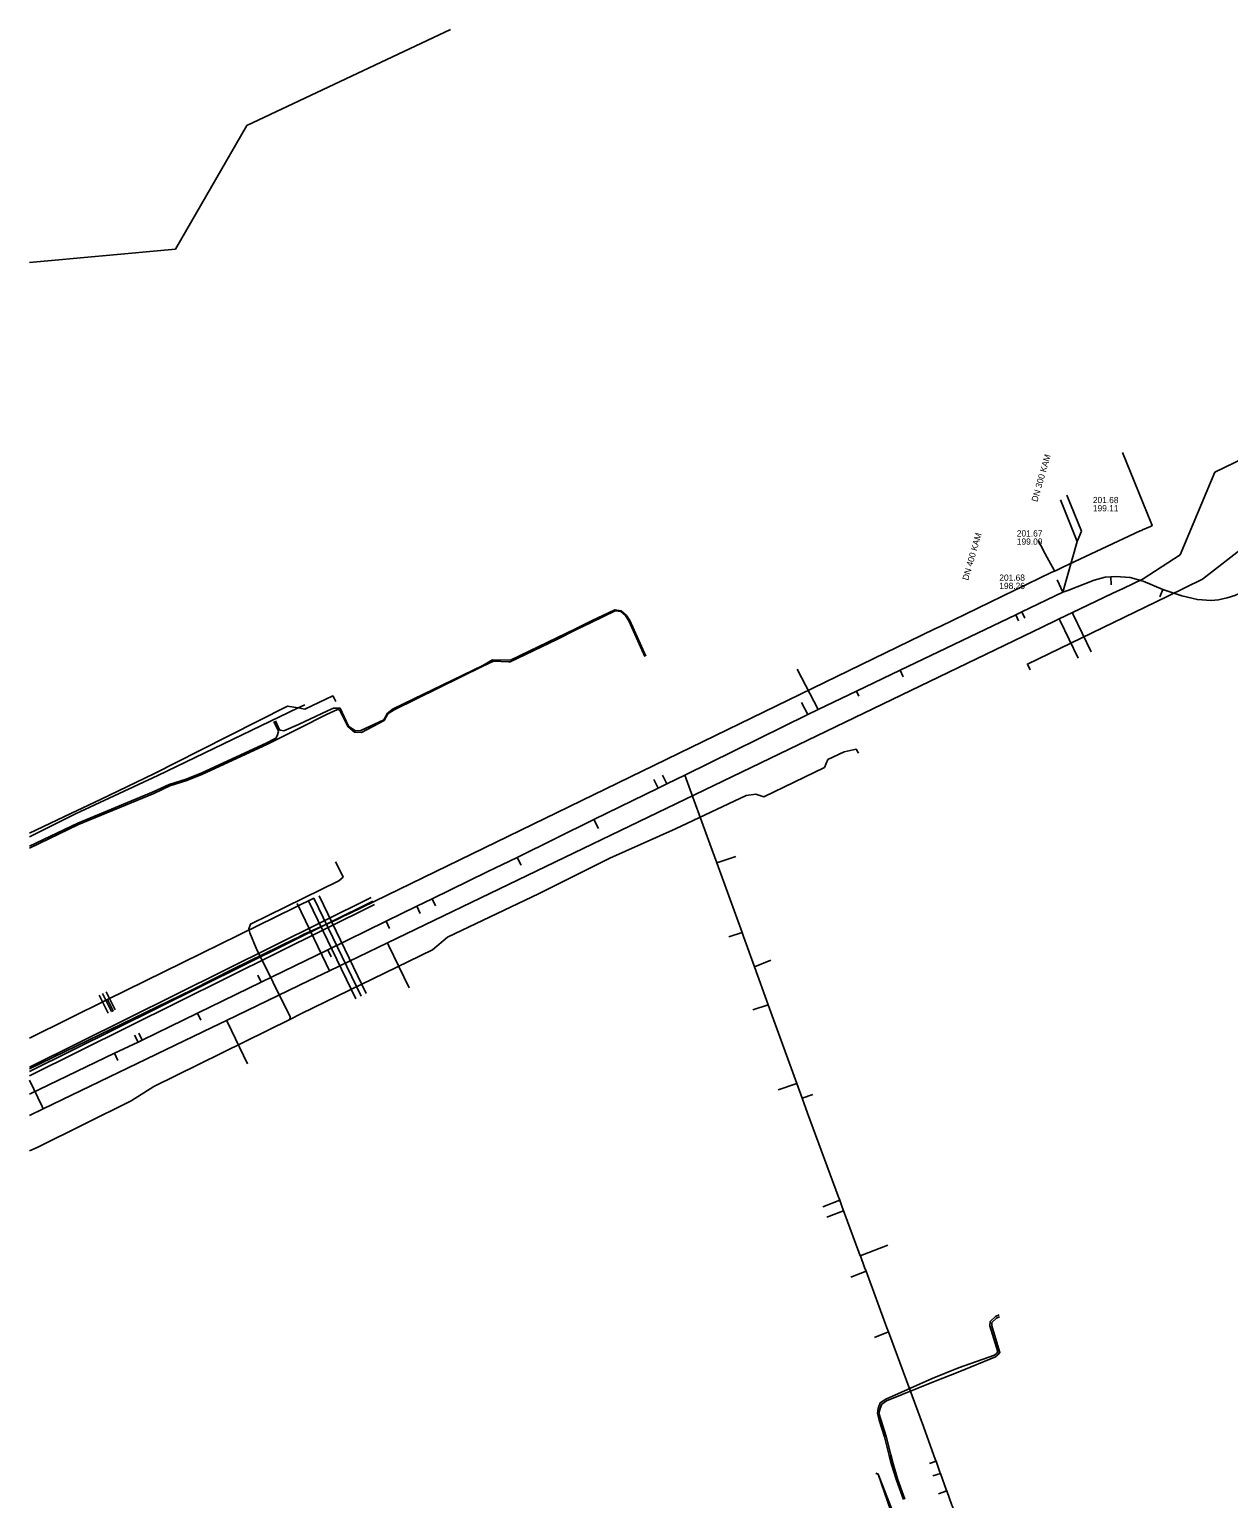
# Model space of a CAD drawing. Extents: x -596228 to -595156, y -1161235 to -1159373.
# Drawn here: x -596228.2 to -596075.1, y -1160804.7 to -1160617.1 of the extents above; entities that cross this region are included whole.
import ezdxf

# ---------------------------------------------------------------- set-up
doc = ezdxf.new("R2010")
doc.units = 0
for name, color, linetype in [('Vrstva 12', 7, 'Continuous'), ('Vrstva 14', 7, 'Continuous'), ('Vrstva 19', 7, 'Continuous'), ('Vrstva 25', 7, 'Continuous'), ('Vrstva 26', 7, 'Continuous'), ('Vrstva 44', 7, 'Continuous'), ('Vrstva 58', 7, 'Continuous'), ('Vrstva 9', 7, 'Continuous')]:
    doc.layers.add(name, color=color, linetype=linetype)

msp = doc.modelspace()

# ---------------------------------------------------------------- linework, layer by layer
at = {"layer": 'Vrstva 12'}
for p, q in [((-596188.689, -1160724.257), (-596189.13, -1160723.36)), ((-596119.86, -1160801.53), (-596120.11, -1160801.44))]:
    msp.add_line(p, q, dxfattribs=at)
for points in [[(-596045.71, -1160660.53), (-596047.56, -1160662.16), (-596055.79, -1160669.46), (-596057.68, -1160671.14), (-596078.44, -1160687.25), (-596082.96, -1160689.5), (-596100.81, -1160698.12), (-596100.47, -1160698.84)], [(-596194.97, -1160743.48), (-596193.47, -1160742.74), (-596176.76, -1160734.58), (-596174.85, -1160732.97), (-596163.12, -1160727.38), (-596154.1, -1160722.91), (-596145.72, -1160719.13), (-596136.7, -1160714.89), (-596135.47, -1160714.71), (-596134.46, -1160715.07), (-596126.73, -1160711.33), (-596126.28, -1160710.3), (-596124.18, -1160709.33), (-596122.67, -1160708.97), (-596122.37, -1160709.47)], [(-596194.97, -1160743.48), (-596194.93, -1160743.15), (-596199.27, -1160734.38), (-596200.06, -1160732.44), (-596200.22, -1160731.93), (-596200.01, -1160731.31), (-596188.7, -1160725.8), (-596188.17, -1160725.31), (-596188.689, -1160724.257)], [(-596228.22, -1160760.275), (-596227.22, -1160759.82), (-596215.24, -1160753.89), (-596212.33, -1160752.02), (-596194.97, -1160743.48)], [(-596102.71, -1160849.4), (-596103.19, -1160846.69), (-596105.77, -1160840.56), (-596109.22, -1160831.71), (-596115.83, -1160813.09), (-596117.57, -1160807.45), (-596119.86, -1160801.53)]]:
    msp.add_lwpolyline(points, dxfattribs=at)
at = {"layer": 'Vrstva 14'}
for points in [[(-596228.22, -1160646.839), (-596209.57, -1160645.15), (-596200.47, -1160629.37), (-596174.46, -1160617.08)], [(-596051.286, -1160662.557), (-596051.688, -1160662.938), (-596058.49, -1160666.8), (-596071.85, -1160671.18), (-596076.86, -1160673.63), (-596081.31, -1160684.16), (-596086.046, -1160687.208), (-596088.561, -1160688.465)], [(-596088.561, -1160688.465), (-596089.903, -1160689.059), (-596091.07, -1160689.611), (-596095.061, -1160691.547), (-596096.731, -1160692.353), (-596097.076, -1160692.525), (-596098.901, -1160693.403), (-596146.846, -1160716.516), (-596182.497, -1160733.699), (-596189.886, -1160737.261), (-596192.511, -1160738.526)], [(-596096.731, -1160692.353), (-596096.621, -1160692.581), (-596094.328, -1160697.338)], [(-596095.061, -1160691.547), (-596094.951, -1160691.774), (-596092.658, -1160696.532)], [(-596189.886, -1160737.261), (-596190.32, -1160736.36), (-596194.023, -1160728.673)], [(-596182.497, -1160733.699), (-596182.359, -1160733.985), (-596179.722, -1160739.456)], [(-596192.511, -1160738.526), (-596203.039, -1160743.601), (-596204.921, -1160744.508), (-596210.857, -1160747.369)], [(-596203.039, -1160743.601), (-596202.93, -1160743.826), (-596200.357, -1160749.165)], [(-596210.857, -1160747.369), (-596226.456, -1160754.888), (-596228.22, -1160755.738)], [(-596226.456, -1160754.888), (-596226.587, -1160754.614), (-596228.22, -1160751.227)]]:
    msp.add_lwpolyline(points, dxfattribs=at)
at = {"layer": 'Vrstva 19'}
msp.add_line((-596085.04, -1160680.01), (-596088.68, -1160671.11), dxfattribs=at)
for points in [[(-596228.22, -1160749.779), (-596207.43, -1160739.7), (-596202.23, -1160737.08), (-596194.32, -1160733.18), (-596194.04, -1160733.04), (-596193.31, -1160732.66), (-596193.19, -1160732.61), (-596193.05, -1160732.55), (-596188.92, -1160730.71), (-596188.75, -1160730.62), (-596188.11, -1160730.28), (-596187.26, -1160729.91), (-596112.69, -1160693.65), (-596111.85, -1160693.26), (-596097.69, -1160686.36), (-596097.24, -1160686.2), (-596096.38, -1160685.8), (-596096.2, -1160685.71), (-596086.42, -1160681.1), (-596086.26, -1160681.04), (-596086.11, -1160680.96), (-596085.11, -1160680.53), (-596084.87, -1160680.41), (-596085.04, -1160680.01)], [(-596097.24, -1160686.2), (-596097.36, -1160686.19), (-596098.52, -1160684.02), (-596099.09, -1160682.99), (-596099.43, -1160682.32)]]:
    msp.add_lwpolyline(points, dxfattribs=at)
at = {"layer": 'Vrstva 25'}
for p, q in [((-596228.22, -1160750.142), (-596184.377, -1160728.366)), ((-596218.247, -1160740.948), (-596191.904, -1160728.014)), ((-596191.904, -1160728.014), (-596185.883, -1160740.502)), ((-596228.22, -1160745.86), (-596218.247, -1160740.948)), ((-596217.733, -1160742.467), (-596218.874, -1160740.173))]:
    msp.add_line(p, q, dxfattribs=at)
msp.add_lwpolyline([(-596218.247, -1160740.948), (-596217.542, -1160742.372), (-596217.733, -1160742.467)], dxfattribs=at)
at = {"layer": 'Vrstva 26'}
for p, q in [((-596228.22, -1160749.584), (-596184.599, -1160727.918)), ((-596186.559, -1160740.828), (-596192.579, -1160728.339)), ((-596191.228, -1160727.688), (-596185.207, -1160740.176)), ((-596184.155, -1160728.813), (-596228.22, -1160750.7)), ((-596218.18, -1160742.69), (-596219.321, -1160740.395)), ((-596218.426, -1160739.95), (-596217.285, -1160742.245))]:
    msp.add_line(p, q, dxfattribs=at)
at = {"layer": 'Vrstva 44'}
for points in [[(-596149.642, -1160697.145), (-596151.644, -1160692.682), (-596152.108, -1160691.915), (-596152.707, -1160691.384), (-596153.455, -1160691.301), (-596156.484, -1160692.792), (-596158.436, -1160693.756), (-596160.876, -1160694.968), (-596166.831, -1160697.809), (-596167.059, -1160697.808), (-596168.981, -1160697.719), (-596170.314, -1160698.385), (-596181.651, -1160703.955), (-596182.469, -1160704.462), (-596182.915, -1160705.293), (-596185.812, -1160706.83), (-596186.699, -1160706.817), (-596187.582, -1160706.088), (-596188.576, -1160704.006), (-596188.881, -1160703.919), (-596190.291, -1160704.528)], [(-596189.4, -1160703.72), (-596188.556, -1160703.726), (-596187.469, -1160706.028), (-596186.603, -1160706.619), (-596185.891, -1160706.611), (-596182.973, -1160705.225), (-596182.5, -1160704.383), (-596181.788, -1160703.819), (-596170.334, -1160698.278), (-596169.075, -1160697.559), (-596166.818, -1160697.629), (-596158.49, -1160693.602), (-596156.473, -1160692.589), (-596153.476, -1160691.172), (-596152.679, -1160691.32), (-596151.993, -1160691.9), (-596151.557, -1160692.556), (-596149.539, -1160697.087)], [(-596189.102, -1160702.896), (-596189.267, -1160702.55), (-596189.481, -1160702.168), (-596193.06, -1160703.853), (-596193.888, -1160703.718), (-596195.252, -1160703.495)], [(-596193.042, -1160703.312), (-596193.888, -1160703.718), (-596211.82, -1160712.32), (-596222.351, -1160717.232), (-596228.22, -1160720.146)], [(-596228.22, -1160719.683), (-596222.936, -1160717.172), (-596219.149, -1160715.396), (-596212.258, -1160712.084), (-596206.471, -1160709.129), (-596195.252, -1160703.495)], [(-596189.4, -1160703.72), (-596190.18, -1160704.06), (-596193.88, -1160705.83), (-596195.72, -1160706.62), (-596196.19, -1160706.562), (-596196.28, -1160706.497), (-596196.82, -1160705.377)], [(-596228.22, -1160721.596), (-596221.966, -1160718.61), (-596212.336, -1160714.62), (-596210.29, -1160713.652), (-596208.133, -1160712.983), (-596206.127, -1160712.181), (-596197.923, -1160708.389), (-596193.731, -1160706.298), (-596190.291, -1160704.528)], [(-596228.22, -1160721.375), (-596222.047, -1160718.428), (-596212.417, -1160714.437), (-596210.363, -1160713.465), (-596208.2, -1160712.795), (-596206.206, -1160711.997), (-596198.01, -1160708.209), (-596196.742, -1160707.576), (-596196.57, -1160707.28), (-596196.421, -1160706.73), (-596196.46, -1160706.583), (-596197, -1160705.463)], [(-596104.429, -1160781.196), (-596104.891, -1160781.4), (-596105.575, -1160782.063), (-596105.589, -1160782.61), (-596104.597, -1160785.935), (-596104.749, -1160786.116), (-596105.028, -1160786.353), (-596109.62, -1160787.973), (-596112.953, -1160789.34), (-596118.871, -1160791.944), (-596119.605, -1160792.443), (-596119.866, -1160793.145), (-596119.946, -1160793.786), (-596119.716, -1160794.628)], [(-596119.524, -1160794.572), (-596119.753, -1160793.734), (-596119.606, -1160793.165), (-596119.399, -1160792.605), (-596118.779, -1160792.185), (-596112.788, -1160789.733), (-596109.435, -1160788.417), (-596104.9, -1160786.571), (-596104.571, -1160786.294), (-596104.319, -1160785.993), (-596105.339, -1160782.576), (-596105.327, -1160782.171), (-596104.761, -1160781.622), (-596104.357, -1160781.435)], [(-596116.644, -1160804.775), (-596117.525, -1160802.312), (-596118.156, -1160800.288), (-596118.457, -1160799.135), (-596119.036, -1160796.777), (-596119.716, -1160794.628)], [(-596116.456, -1160804.705), (-596117.335, -1160802.248), (-596117.964, -1160800.233), (-596118.263, -1160799.085), (-596118.844, -1160796.723), (-596119.524, -1160794.572)]]:
    msp.add_lwpolyline(points, dxfattribs=at)
at = {"layer": 'Vrstva 58'}
msp.add_lwpolyline([(-596102.709, -1160849.404), (-596103.193, -1160846.688), (-596105.769, -1160840.558), (-596109.217, -1160831.712), (-596115.827, -1160813.087), (-596117.85, -1160807.323), (-596119.861, -1160801.533), (-596120.14, -1160801.426)], dxfattribs=at)
at = {"layer": 'Vrstva 9'}
for p, q in [((-596096.589, -1160677.156), (-596094.448, -1160682.447)), ((-596096.589, -1160677.156), (-596094.448, -1160682.447)), ((-596095.76, -1160676.534), (-596093.885, -1160681.147)), ((-596095.76, -1160676.534), (-596093.885, -1160681.147)), ((-596093.885, -1160681.147), (-596094.448, -1160682.447)), ((-596093.885, -1160681.147), (-596094.448, -1160682.447)), ((-596094.448, -1160682.447), (-596096.27, -1160688.95)), ((-596090.101, -1160687.983), (-596090.159, -1160686.985)), ((-596097.001, -1160687.335), (-596096.27, -1160688.95)), ((-596083.888, -1160689.53), (-596083.498, -1160688.609)), ((-596101.924, -1160692.605), (-596102.277, -1160691.827)), ((-596101.144, -1160692.252), (-596101.509, -1160691.455)), ((-596130.204, -1160698.751), (-596127.53, -1160703.922)), ((-596116.662, -1160699.72), (-596117.037, -1160698.892)), ((-596122.323, -1160702.197), (-596122.611, -1160701.566)), ((-596129.629, -1160703.03), (-596128.835, -1160704.556)), ((-596148.515, -1160712.863), (-596147.965, -1160713.955)), ((-596147.402, -1160712.304), (-596146.851, -1160713.409)), ((-596144.552, -1160712.279), (-596141.329, -1160721.043)), ((-596155.564, -1160719.101), (-596156.138, -1160717.962)), ((-596165.438, -1160723.801), (-596165.951, -1160722.786)), ((-596138.033, -1160722.683), (-596140.441, -1160723.495)), ((-596176.38, -1160728.993), (-596176.818, -1160728.094)), ((-596178.31, -1160729.934), (-596178.749, -1160729.035)), ((-596182.243, -1160731.85), (-596182.681, -1160730.951)), ((-596138.906, -1160732.948), (-596137.224, -1160732.38)), ((-596189.676, -1160735.474), (-596190.115, -1160734.575)), ((-596133.55, -1160735.895), (-596135.633, -1160736.748)), ((-596199.073, -1160737.829), (-596198.635, -1160738.727)), ((-596206.33, -1160743.591), (-596206.769, -1160742.692)), ((-596135.88, -1160742.269), (-596133.89, -1160741.598)), ((-596214.249, -1160745.211), (-596213.817, -1160746.113)), ((-596214.785, -1160745.467), (-596214.353, -1160746.369)), ((-596216.914, -1160748.704), (-596217.346, -1160747.802)), ((-596132.614, -1160752.468), (-596130.243, -1160751.671)), ((-596128.194, -1160753.055), (-596129.572, -1160753.523)), ((-596126.92, -1160767.422), (-596124.763, -1160766.569)), ((-596126.395, -1160768.739), (-596124.27, -1160767.9)), ((-596118.633, -1160772.306), (-596122.137, -1160773.651)), ((-596123.367, -1160776.401), (-596121.41, -1160775.628)), ((-596120.335, -1160784.07), (-596118.546, -1160783.365)), ((-596113.32, -1160800.174), (-596112.471, -1160799.885)), ((-596112.875, -1160801.759), (-596111.904, -1160801.466)), ((-596112.161, -1160804.041), (-596111.111, -1160803.657))]:
    msp.add_line(p, q, dxfattribs=at)
for points in [[(-596052.015, -1160680.279), (-596073.218, -1160688.852), (-596074.33, -1160689.336), (-596075.288, -1160689.635), (-596076.394, -1160689.908), (-596077.34, -1160690.004), (-596079.103, -1160689.875), (-596081.087, -1160689.406), (-596083.498, -1160688.609)], [(-596083.498, -1160688.609), (-596086.048, -1160687.529), (-596087.672, -1160687.068), (-596089.535, -1160686.948), (-596090.159, -1160686.985), (-596090.898, -1160687.028), (-596092.301, -1160687.389), (-596095.643, -1160688.704), (-596096.27, -1160688.95)], [(-596096.27, -1160688.95), (-596101.509, -1160691.455), (-596102.277, -1160691.827), (-596117.037, -1160698.892), (-596122.611, -1160701.566), (-596127.53, -1160703.922)], [(-596127.53, -1160703.922), (-596128.835, -1160704.556), (-596144.552, -1160712.279)], [(-596144.552, -1160712.279), (-596146.851, -1160713.409), (-596147.965, -1160713.955), (-596156.138, -1160717.962), (-596165.951, -1160722.786), (-596169.762, -1160724.654)], [(-596141.329, -1160721.043), (-596140.441, -1160723.495), (-596137.224, -1160732.38), (-596137.034, -1160732.901), (-596135.633, -1160736.748), (-596133.89, -1160741.598), (-596130.243, -1160751.671), (-596129.572, -1160753.523), (-596128.873, -1160755.454)], [(-596169.762, -1160724.654), (-596176.818, -1160728.094), (-596178.749, -1160729.035), (-596182.681, -1160730.951), (-596190.115, -1160734.575), (-596198.635, -1160738.727), (-596206.769, -1160742.692), (-596212.075, -1160745.278)], [(-596212.075, -1160745.278), (-596213.817, -1160746.113), (-596214.353, -1160746.369), (-596217.346, -1160747.802), (-596228.22, -1160753.009)], [(-596128.873, -1160755.454), (-596124.962, -1160766.032), (-596124.763, -1160766.569), (-596124.434, -1160767.459), (-596124.355, -1160767.672), (-596124.27, -1160767.9), (-596124.187, -1160768.125), (-596122.316, -1160773.18), (-596122.137, -1160773.651), (-596122.135, -1160773.657), (-596121.594, -1160775.133), (-596121.41, -1160775.628), (-596118.739, -1160782.844), (-596118.546, -1160783.365), (-596114.075, -1160795.455)], [(-596114.075, -1160795.455), (-596112.527, -1160799.729), (-596112.471, -1160799.885), (-596111.968, -1160801.29), (-596111.904, -1160801.466), (-596111.131, -1160803.602), (-596111.111, -1160803.657), (-596110.455, -1160805.479), (-596110.386, -1160805.67), (-596109.419, -1160808.342), (-596109.338, -1160808.567), (-596108.224, -1160811.653), (-596108.16, -1160811.83), (-596103.519, -1160824.687), (-596103.432, -1160824.934), (-596103.43, -1160824.94), (-596103.34, -1160825.188), (-596099.171, -1160836.727)]]:
    msp.add_lwpolyline(points, dxfattribs=at)

# ---------------------------------------------------------------- texts
at = {"layer": 'Vrstva 12'}
for s, p in [('DN 300 KAM', (-596099.539, -1160677.464)), ('DN 400 KAM', (-596108.362, -1160687.489))]:
    msp.add_text(s, height=0.8, rotation=74, dxfattribs=at).set_placement(p)
for s, p in [('201.68', (-596092.446, -1160677.567)), ('199.11', (-596092.446, -1160678.617)), ('201.67', (-596102.157, -1160681.826)), ('199.09', (-596102.157, -1160682.876)), ('201.68', (-596104.393, -1160687.478)), ('198.26', (-596104.393, -1160688.528))]:
    msp.add_text(s, height=0.8, dxfattribs=at).set_placement(p)

doc.saveas('drawing.dxf')
